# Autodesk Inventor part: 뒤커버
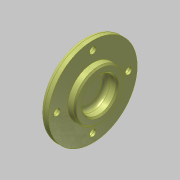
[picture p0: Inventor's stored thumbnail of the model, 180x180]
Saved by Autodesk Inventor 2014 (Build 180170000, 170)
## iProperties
Created: 2015-12
Part Number: 뒤커버
Document SubType Name: Modeling
Designer: mdu
Density: 2.71 g/cm^3
Material: 알루미늄 6061
Mass: 56.1988 g
Surface Area: 84.0425 cm^2
Volume: 20.7376 cm^3
Appearance: 알루미늄 - 평지
Author: mdu
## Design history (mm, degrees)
sketch "스케치1"
  geometry: L1 (-7, 0)-(7, 0); L2 (-7, 0)-(-7, 15.539); L3 (-7, 15.539)-(-4, 18.5); L4 (-4, 18.5)-(-4, 31); L5 (-4, 31)-(2, 31); L6 (2, 31)-(2, 17.5); L7 (2, 17.5)-(7, 17.5); L8 (7, 17.5)-(7, 0); 2 further points
  constraints: 16 end point, 4 parallel, 2 perpendicular, 1 coincident, 1 horizontal, 1 midpoint
  dimensions: "d0" = 14 distance of L1.start L1.end; "d1" = 62 diameter of L5 L1; "d2" = 35 diameter of L7 L1; "d3" = 37 diameter of L3.end L1; "d4" = 3 distance between parallel lines of L4 L2; "d5" = 6 distance of L4.end L5.end
revolve "회전1" sketch "스케치1" stored, may be unused: angle "d6" = 90 deg
sketch "스케치2" dims "d32" = 50
  geometry: 3 further points
  constraints: 2 vertical alignment, 1 coincident, 2 other
hole "구멍1" sketch "스케치2" at (0, 25) diameter "d8" = 4.5; stored, may be unused: countersink angle "d12" = 90 deg, drill point angle "d14" = 118 deg; dims "d9" = 6, "d10" = 8, "d11" = 4.4, "d13" = 8
hole "구멍2" diameter "d20" = 24; stored, may be unused: countersink angle "d24" = 90 deg, drill point angle "d26" = 0 deg; dims "d18" = 10, "d19" = 10, "d21" = 6, "d22" = 8, "d23" = 4.4, "d25" = 8
fillet "모깎기1" dims "d27" = 3
fillet "모깎기2" dims "d28" = 3
chamfer "모따기1" distance "d29" = 1; stored, may be unused: second distance "d30" = 2, angle "d31" = 45 deg
node "솔리드1"
pattern_circular "원형 패턴1" dims angle "d16" = 360 deg
